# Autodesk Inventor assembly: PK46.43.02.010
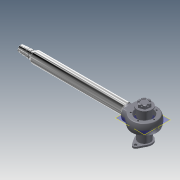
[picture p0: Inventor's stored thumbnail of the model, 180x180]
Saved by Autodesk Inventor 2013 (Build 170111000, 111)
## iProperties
Shininess: 64.0
Length Units: 11269
Angle Units: 11279
Time Units: 11290
Mass Units: 11283
Length Display Precision: 3
Angle Display Precision: 2
Compacted: True
Created: 2004-11
Part Number: PK46.43.02.010
Document SubType Name: Assembly
Designer: ELarisa
Manufacturer: Standard
Standards Organization: Custom
Mass: 53559.8 g
Surface Area: 5360.37 cm^2
Volume: 6814.23 cm^3
Density: 7.86 g/cm^3
Density: 0.0
Volumn: 0.0
Area: 0.0
PropertySet Name: Model Information
Control State: 0
Master: False
Checked Out: False
Checked Out Date: 2008-10-09
Last Check In Date: 2008-10-09
Author: ELarisa
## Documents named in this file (7)
- D:\FrontLoaderVault\Data\Assy, Chassis, Front\PK46.43.02.010.iam
- D:\FrontLoaderVault\Data\Assy, Chassis, Front\PK46.43.02.001.ipt
- D:\FrontLoaderVault\Data\Assy, Chassis, Front\PK46.43.02.008.ipt
- D:\FrontLoaderVault\Data\Assy, Chassis, Front\PK46.25.00.010.iam
- D:\FrontLoaderVault\Data\Assy, Chassis, Front\PK46.25.00.005.ipt
- D:\FrontLoaderVault\Data\Assy, Chassis, Front\PK46.25.00.008.ipt
- D:\FrontLoaderVault\Data\Assy, Chassis, Front\PK46.25.00.007.ipt
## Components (7 placed, 6 different names)
1. PK46.43.02.001:1 — Insert:1
2. PK46.43.02.008:1 — Insert:1, Mate:1, Mate:2
3. PK46.25.00.007:1
4. PK46.25.00.008:1
5. PK46.25.00.005:2
6. PK46.25.00.005:1
7. PK46.25.00.010:1 [sub-assembly]
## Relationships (3: Mate 2, Insert 1)
- Insert:1: PK46.43.02.001:1 ↔ PK46.43.02.008:1
- Mate:1: PK46.43.02.008:1
- Mate:2: PK46.43.02.008:1
